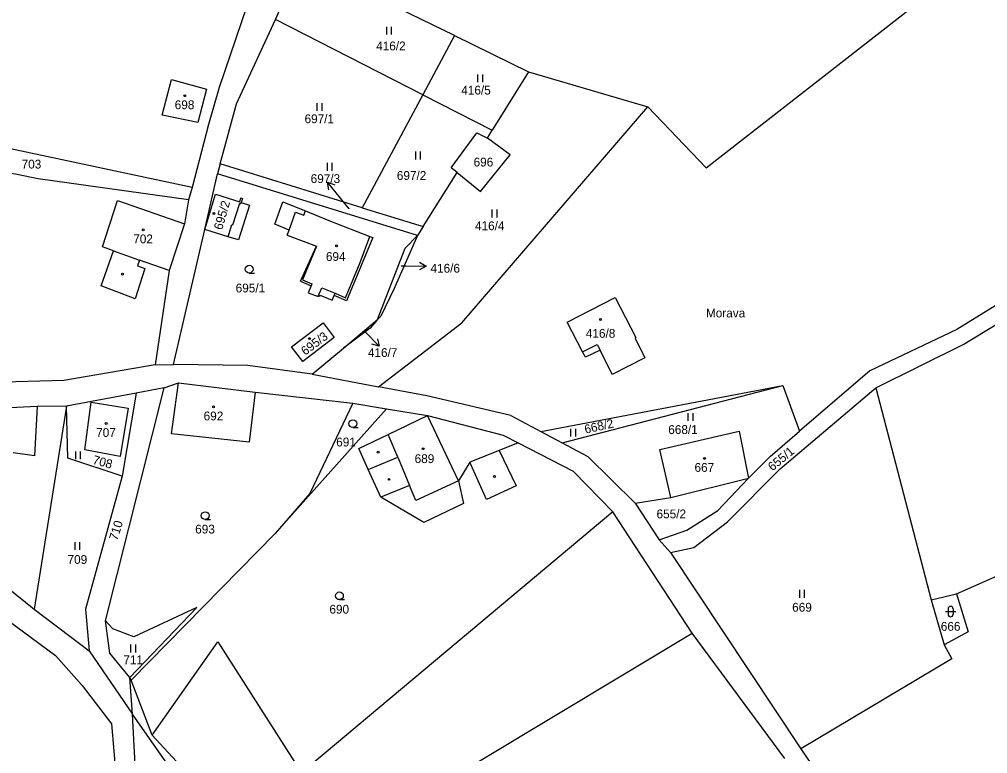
# Model space of a CAD drawing. Extents: x -670359 to -668019, y -978807 to -976674.
# Drawn here: x -668641.1 to -668454.3, y -977743.3 to -977601.7 of the extents above; entities that cross this region are included whole.
import ezdxf

# ---------------------------------------------------------------- set-up
doc = ezdxf.new("R2010")
doc.units = 0
for name, color, linetype in [('Hranice parcel', 7, 'Continuous'), ('Parcelní čísla', 7, 'Continuous'), ('Pop  PČ popisy', 7, 'Continuous'), ('Vnitřní kresba', 7, 'Continuous'), ('Značky budov', 7, 'Continuous'), ('Značky kultur', 7, 'Continuous')]:
    doc.layers.add(name, color=color, linetype=linetype)

msp = doc.modelspace()

# ---------------------------------------------------------------- linework, layer by layer
at = {"layer": 'Hranice parcel'}
for p, q in [((-668557.18, -977604.87), (-668586.71, -977590.44)), ((-668563.3, -977616.26), (-668591.75, -977601.77)), ((-668557.18, -977604.87), (-668563.3, -977616.26)), ((-668557.18, -977604.87), (-668542.9, -977611.84)), ((-668542.9, -977611.84), (-668519.87, -977618.61)), ((-668563.3, -977616.26), (-668575, -977638.05)), ((-668563.3, -977616.26), (-668549.89, -977623.09)), ((-668602.37, -977629.57), (-668599.22, -977618)), ((-668605.37, -977642.22), (-668602.9, -977631.5)), ((-668563.24, -977641.7), (-668556.67, -977631.25)), ((-668605.37, -977642.22), (-668603.32, -977635.42)), ((-668603.32, -977635.42), (-668598.63, -977636.89)), ((-668598.63, -977636.89), (-668598.41, -977636.17)), ((-668598.41, -977636.17), (-668598.11, -977636.26)), ((-668598.11, -977636.26), (-668598.36, -977637.06)), ((-668598.36, -977637.06), (-668596.76, -977637.56)), ((-668596.76, -977637.56), (-668598.87, -977644.27)), ((-668585.92, -977638.68), (-668581.45, -977640.5)), ((-668575, -977638.05), (-668563.24, -977641.7)), ((-668600.87, -977643.66), (-668605.37, -977642.22)), ((-668589.47, -977643.33), (-668589.11, -977642.36)), ((-668598.87, -977644.27), (-668600.87, -977643.66)), ((-668589.47, -977643.33), (-668583.84, -977645.49)), ((-668573.52, -977643.59), (-668572.97, -977643.8)), ((-668586.88, -977652.2), (-668584.86, -977653.08)), ((-668584.86, -977653.08), (-668585.39, -977654.43)), ((-668585.39, -977654.43), (-668583.52, -977655.19)), ((-668583.52, -977655.19), (-668583.44, -977655)), ((-668583.44, -977655), (-668583.18, -977655.11)), ((-668583.18, -977655.11), (-668583.09, -977654.89)), ((-668583.09, -977654.89), (-668580.76, -977655.85)), ((-668580.76, -977655.85), (-668580.41, -977655)), ((-668535.43, -977660.12), (-668526.2, -977655.34)), ((-668526.2, -977655.34), (-668522.22, -977663.1)), ((-668588.63, -977664.88), (-668582.54, -977660.26)), ((-668582.54, -977660.26), (-668580.43, -977663.1)), ((-668532.5, -977665.86), (-668535.43, -977660.12)), ((-668580.43, -977663.1), (-668586.44, -977667.7)), ((-668522.22, -977663.1), (-668522.33, -977663.17)), ((-668522.33, -977663.17), (-668520.43, -977666.96)), ((-668586.44, -977667.7), (-668588.63, -977664.88)), ((-668531.93, -977666.88), (-668532.5, -977665.86)), ((-668529.1, -977665.48), (-668531.93, -977666.88)), ((-668526.78, -977670.2), (-668529.1, -977665.48)), ((-668520.43, -977666.96), (-668526.78, -977670.2)), ((-668536.38, -977683.38), (-668493.85, -977672.35)), ((-668540.55, -977681.17), (-668536.38, -977683.38)), ((-668536.38, -977683.38), (-668531.45, -977686)), ((-668506.35, -977696.41), (-668500.44, -977690.21)), ((-668512.33, -977700.2), (-668506.35, -977696.41)), ((-668517.68, -977702.09), (-668512.33, -977700.2))]:
    msp.add_line(p, q, dxfattribs=at)
for points in [[(-668508.63, -977630.34), (-668419.28, -977560.69)], [(-668589.87, -977577.38), (-668602.57, -977614.87)], [(-668591.75, -977601.77), (-668586.71, -977590.44)], [(-668599.22, -977618), (-668591.75, -977601.77)], [(-668542.9, -977611.84), (-668549.89, -977623.09)], [(-668613.61, -977620.19), (-668611.77, -977613.34)], [(-668611.77, -977613.34), (-668605.01, -977615.16)], [(-668602.57, -977614.87), (-668604.65, -977622.03)], [(-668605.01, -977615.16), (-668606.68, -977621.61)], [(-668555.76, -977660.24), (-668519.87, -977618.61)], [(-668519.87, -977618.61), (-668508.63, -977630.34)], [(-668606.68, -977621.61), (-668613.61, -977620.19)], [(-668607.82, -977634.15), (-668664.97, -977621.98)], [(-668604.65, -977622.03), (-668607.82, -977634.15)], [(-668557.84, -977630.33), (-668552.87, -977623.62)], [(-668552.87, -977623.62), (-668550.83, -977624.66)], [(-668550.83, -977624.66), (-668549.89, -977623.09)], [(-668546.46, -977627.85), (-668550.83, -977624.66)], [(-668637.54, -977632.46), (-668666.42, -977626.62)], [(-668552.15, -977634.93), (-668546.46, -977627.85)], [(-668403.78, -977626.71), (-668460.27, -977661.53)], [(-668602.37, -977629.57), (-668602.9, -977631.5)], [(-668575, -977638.05), (-668602.37, -977629.57)], [(-668458.93, -977664.38), (-668402.04, -977629.73)], [(-668564.3, -977643.39), (-668602.9, -977631.5)], [(-668556.67, -977631.25), (-668557.84, -977630.33)], [(-668556.67, -977631.25), (-668552.15, -977634.93)], [(-668608.5, -977636.5), (-668637.54, -977632.46)], [(-668607.82, -977634.15), (-668608.5, -977636.5)], [(-668625.09, -977645.61), (-668622.18, -977636.66)], [(-668622.18, -977636.66), (-668609.3, -977641.17)], [(-668608.5, -977636.5), (-668609.3, -977641.17)], [(-668591.86, -977641.22), (-668590.3, -977636.9)], [(-668590.3, -977636.9), (-668585.92, -977638.68)], [(-668581.45, -977640.5), (-668573.52, -977643.59)], [(-668609.3, -977641.17), (-668612.22, -977650.13)], [(-668611.39, -977668.3), (-668605.37, -977642.22)], [(-668589.11, -977642.36), (-668591.86, -977641.22)], [(-668563.24, -977641.7), (-668564.3, -977643.39)], [(-668572.97, -977643.8), (-668578.04, -977656.03)], [(-668564.3, -977643.39), (-668568.85, -977653.65), (-668571.43, -977658.96), (-668572.07, -977659.62)], [(-668566.71, -977645.87), (-668564.3, -977643.39)], [(-668625.36, -977653.13), (-668623.01, -977646.34)], [(-668623.01, -977646.34), (-668625.09, -977645.61)], [(-668586.88, -977652.2), (-668583.84, -977645.49)], [(-668572.07, -977659.62), (-668566.71, -977645.87)], [(-668617.98, -977648.19), (-668618.38, -977649.23)], [(-668612.22, -977650.13), (-668617.98, -977648.19)], [(-668616.94, -977649.79), (-668618.8, -977655.63)], [(-668618.38, -977649.23), (-668616.94, -977649.79)], [(-668612.22, -977650.13), (-668614.92, -977668.36)], [(-668618.8, -977655.63), (-668625.36, -977653.13)], [(-668578.04, -977656.03), (-668580.41, -977655)], [(-668572.07, -977659.62), (-668573.45, -977661.25), (-668578.62, -977665.1)], [(-668578.62, -977665.1), (-668572.07, -977659.62)], [(-668571.86, -977672.56), (-668555.76, -977660.24)], [(-668460.27, -977661.53), (-668477.05, -977669.51)], [(-668584.63, -977670.12), (-668578.62, -977665.1)], [(-668475.88, -977672.75), (-668458.93, -977664.38)], [(-668614.92, -977668.36), (-668632.55, -977671.35)], [(-668614.92, -977668.36), (-668611.39, -977668.3)], [(-668597.06, -977668.49), (-668611.39, -977668.3)], [(-668584.63, -977670.12), (-668597.06, -977668.49)], [(-668584.63, -977670.12), (-668571.86, -977672.56)], [(-668477.05, -977669.51), (-668490.6, -977681.15)], [(-668632.55, -977671.35), (-668651.2, -977671.86)], [(-668613.23, -977672.8), (-668610.47, -977671.78)], [(-668611.78, -977681.65), (-668610.47, -977671.78)], [(-668610.47, -977671.78), (-668595.64, -977673.58)], [(-668562.51, -977674.34), (-668571.86, -977672.56)], [(-668540.55, -977681.17), (-668493.85, -977672.35)], [(-668494.37, -977688.42), (-668475.88, -977672.75)], [(-668493.85, -977672.35), (-668490.6, -977681.15)], [(-668475.88, -977672.75), (-668465.23, -977713.62)], [(-668618.62, -977673.79), (-668632.08, -977676.32)], [(-668624.53, -977717.7), (-668613.23, -977672.8)], [(-668618.62, -977673.79), (-668621.32, -977689.79)], [(-668613.23, -977672.8), (-668618.62, -977673.79)], [(-668595.64, -977673.58), (-668596.78, -977683.22)], [(-668595.64, -977673.58), (-668576.82, -977675.76)], [(-668546.31, -977678.11), (-668562.51, -977674.34)], [(-668637.69, -977676.34), (-668654.82, -977677.21)], [(-668632.08, -977676.32), (-668638.3, -977715.42)], [(-668637.69, -977676.34), (-668638.2, -977685.9)], [(-668632.08, -977676.32), (-668637.69, -977676.34)], [(-668631.79, -977686.32), (-668632.08, -977676.32)], [(-668628.51, -977684.73), (-668627.27, -977675.53)], [(-668627.27, -977675.53), (-668620.15, -977676.67)], [(-668576.82, -977675.76), (-668585.13, -977693.13)], [(-668576.82, -977675.76), (-668570.3, -977676.8)], [(-668620.15, -977676.67), (-668621.71, -977686.02)], [(-668570.3, -977676.8), (-668591.8, -977700.84)], [(-668570.3, -977676.8), (-668562.4, -977678.11)], [(-668569.98, -977681.76), (-668562.4, -977678.11)], [(-668562.4, -977678.11), (-668547.8, -977681.9)], [(-668546.31, -977678.11), (-668540.55, -977681.17)], [(-668596.78, -977683.22), (-668611.78, -977681.65)], [(-668575.65, -977684.5), (-668569.98, -977681.76)], [(-668547.8, -977681.9), (-668544.92, -977683.38)], [(-668517.55, -977684.65), (-668502.28, -977681.1)], [(-668502.28, -977681.1), (-668500.44, -977690.21)], [(-668496.29, -977686.04), (-668490.6, -977681.15)], [(-668544.92, -977683.38), (-668548.55, -977684.84)], [(-668544.92, -977683.38), (-668534.27, -977688.86)], [(-668638.2, -977685.9), (-668642.36, -977685.33)], [(-668621.71, -977686.02), (-668628.51, -977684.73)], [(-668573.82, -977688.51), (-668575.65, -977684.5)], [(-668548.55, -977684.84), (-668545.26, -977691.68)], [(-668515.47, -977693.92), (-668517.55, -977684.65)], [(-668621.32, -977689.79), (-668631.79, -977686.32)], [(-668554.23, -977687.12), (-668556.44, -977690.72)], [(-668551.04, -977694.27), (-668554.23, -977687.12)], [(-668531.45, -977686), (-668522.32, -977695.04)], [(-668500.44, -977690.21), (-668496.29, -977686.04)], [(-668571.37, -977693.88), (-668573.82, -977688.51)], [(-668534.27, -977688.86), (-668526.62, -977696.65)], [(-668504.5, -977698.63), (-668494.37, -977688.42)], [(-668621.32, -977689.79), (-668628.41, -977715.46)], [(-668556.44, -977690.72), (-668555.47, -977695.08)], [(-668515.47, -977693.92), (-668500.44, -977690.21)], [(-668585.13, -977693.13), (-668591.8, -977700.84)], [(-668545.26, -977691.68), (-668551.04, -977694.27)], [(-668563.13, -977698.73), (-668571.37, -977693.88)], [(-668555.47, -977695.08), (-668563.13, -977698.73)], [(-668522.32, -977695.04), (-668515.47, -977693.92)], [(-668522.32, -977695.04), (-668517.68, -977702.09)], [(-668526.62, -977696.65), (-668586.69, -977746.97)], [(-668511.35, -977720.08), (-668526.62, -977696.65)], [(-668659.7, -977698.24), (-668638.3, -977715.42)], [(-668511, -977703.53), (-668504.5, -977698.63)], [(-668591.8, -977700.84), (-668619.55, -977729.15)], [(-668517.68, -977702.09), (-668515.52, -977704.49)], [(-668515.52, -977704.49), (-668511, -977703.53)], [(-668515.52, -977704.49), (-668490.35, -977742.35)], [(-668460.3, -977712.51), (-668440.7, -977703.84)], [(-668654.53, -977709.38), (-668634.16, -977724.39)], [(-668465.23, -977713.62), (-668460.3, -977712.51)], [(-668465.23, -977713.62), (-668462.73, -977722.35)], [(-668460.3, -977712.51), (-668458.08, -977719.79)], [(-668638.3, -977715.42), (-668631.43, -977720.64)], [(-668628.41, -977715.46), (-668627.68, -977723.45)], [(-668619.85, -977728.6), (-668606.9, -977715.15)], [(-668606.9, -977715.15), (-668619.09, -977720.77)], [(-668623.67, -977723.94), (-668624.53, -977717.7)], [(-668624.53, -977717.7), (-668623.1, -977719.25)], [(-668619.09, -977720.77), (-668623.1, -977719.25)], [(-668631.43, -977720.64), (-668627.68, -977723.45)], [(-668493.46, -977744.24), (-668511.35, -977720.08)], [(-668458.08, -977719.79), (-668462.73, -977722.35)], [(-668462.73, -977722.35), (-668461.23, -977725.04)], [(-668634.16, -977724.39), (-668629.06, -977730.17)], [(-668627.68, -977723.45), (-668619.3, -977735.7)], [(-668619.85, -977728.6), (-668623.67, -977723.94)], [(-668461.23, -977725.04), (-668490.35, -977742.35)], [(-668619.55, -977729.15), (-668619.85, -977728.6)], [(-668619.3, -977735.7), (-668619.85, -977728.6)], [(-668629.06, -977730.17), (-668623.4, -977737.55)], [(-668615.55, -977739.75), (-668619.55, -977729.15)], [(-668591.77, -977775.03), (-668619.3, -977735.7)], [(-668618.64, -977749.04), (-668619.3, -977735.7)], [(-668623.4, -977737.55), (-668622.47, -977748.11)], [(-668599.16, -977757.41), (-668615.55, -977739.75)], [(-668490.35, -977742.35), (-668466.44, -977777.44)]]:
    msp.add_lwpolyline(points, dxfattribs=at)
at = {"layer": 'Parcelní čísla'}
for p, q in [((-668581.44, -977634.57), (-668581.66, -977633.09)), ((-668577.54, -977638.27), (-668579.17, -977636.22)), ((-668567.46, -977649.26), (-668566.65, -977649.27)), ((-668563.94, -977648.54), (-668562.65, -977649.31)), ((-668574.52, -977661.85), (-668574.49, -977661.89)), ((-668572.07, -977663.31), (-668571.71, -977664.76))]:
    msp.add_line(p, q, dxfattribs=at)
for points in [[(-668579.17, -977636.22), (-668581.66, -977633.09), (-668580.26, -977633.64)], [(-668566.65, -977649.27), (-668562.65, -977649.31), (-668563.96, -977650.04)], [(-668574.49, -977661.89), (-668571.71, -977664.76), (-668573.15, -977664.35)]]:
    msp.add_lwpolyline(points, dxfattribs=at)
at = {"layer": 'Vnitřní kresba'}
for p, q in [((-668599.96, -977641.32), (-668598.62, -977637.2)), ((-668598.62, -977637.2), (-668598.43, -977637.27)), ((-668598.43, -977637.27), (-668598.36, -977637.06)), ((-668589.11, -977642.36), (-668587.84, -977638.9)), ((-668587.84, -977638.9), (-668586.23, -977639.49)), ((-668586.23, -977639.49), (-668585.92, -977638.68)), ((-668600.87, -977643.66), (-668600.13, -977641.27)), ((-668600.13, -977641.27), (-668599.96, -977641.32)), ((-668575.37, -977648.62), (-668573.52, -977643.59)), ((-668583.84, -977645.49), (-668586.53, -977651.98)), ((-668578.2, -977655.4), (-668575.37, -977648.62)), ((-668586.53, -977651.98), (-668584.71, -977652.7)), ((-668584.71, -977652.7), (-668584.86, -977653.08)), ((-668583.44, -977655), (-668582.8, -977653.47)), ((-668582.8, -977653.47), (-668580.23, -977654.55)), ((-668580.23, -977654.55), (-668578.2, -977655.4)), ((-668532.5, -977665.86), (-668529.63, -977664.39)), ((-668529.63, -977664.39), (-668529.1, -977665.48))]:
    msp.add_line(p, q, dxfattribs=at)
for points in [[(-668623.01, -977646.34), (-668617.98, -977648.19)], [(-668580.41, -977655), (-668580.23, -977654.55)], [(-668556.44, -977690.72), (-668562.4, -977678.11)], [(-668568.15, -977686.15), (-668569.98, -977681.76)], [(-668548.55, -977684.84), (-668554.23, -977687.12)], [(-668573.82, -977688.51), (-668568.15, -977686.15)], [(-668568.15, -977686.15), (-668565.88, -977691.59)], [(-668556.44, -977690.72), (-668564.66, -977694.52)], [(-668565.88, -977691.59), (-668571.37, -977693.88)], [(-668564.66, -977694.52), (-668565.88, -977691.59)], [(-668578.19, -977760.23), (-668511.35, -977720.08)], [(-668615.55, -977739.75), (-668602.87, -977721.74)], [(-668602.87, -977721.74), (-668586.69, -977746.97)]]:
    msp.add_lwpolyline(points, dxfattribs=at)
at = {"layer": 'Značky budov'}
for centre in [(-668609.24, -977616.45), (-668603.6, -977639.16), (-668617.24, -977642.31), (-668579.93, -977645.41), (-668529.04, -977659.6), (-668585.16, -977663.28), (-668603.66, -977676.45), (-668624.4, -977679.64), (-668563.23, -977684.51), (-668508.94, -977686.37)]:
    msp.add_circle(centre, 0.175, dxfattribs=at)
at = {"layer": 'Značky kultur'}
for p, q in [((-668570.31, -977603.15), (-668570.31, -977604.65)), ((-668569.31, -977604.65), (-668569.31, -977603.15)), ((-668552.73, -977612.36), (-668552.73, -977613.86)), ((-668551.73, -977613.86), (-668551.73, -977612.36)), ((-668583.74, -977617.88), (-668583.74, -977619.38)), ((-668582.74, -977619.38), (-668582.74, -977617.88)), ((-668564.74, -977627.24), (-668564.74, -977628.74)), ((-668563.74, -977628.74), (-668563.74, -977627.24)), ((-668581.76, -977629.42), (-668581.76, -977630.92)), ((-668580.76, -977630.92), (-668580.76, -977629.42)), ((-668549.95, -977638.41), (-668549.95, -977639.91)), ((-668548.95, -977639.91), (-668548.95, -977638.41)), ((-668596.8, -977650.65), (-668595.8, -977650.65)), ((-668512.15, -977677.66), (-668512.15, -977679.16)), ((-668511.15, -977679.16), (-668511.15, -977677.66)), ((-668576.8, -977680.42), (-668575.8, -977680.42)), ((-668534.8, -977680.66), (-668534.8, -977682.16)), ((-668533.8, -977682.16), (-668533.8, -977680.66)), ((-668630.33, -977685.02), (-668630.33, -977686.52)), ((-668629.33, -977686.52), (-668629.33, -977685.02)), ((-668605.29, -977698.16), (-668604.29, -977698.16)), ((-668630.46, -977702.52), (-668630.46, -977704.02)), ((-668629.46, -977704.02), (-668629.46, -977702.52)), ((-668490.64, -977711.73), (-668490.64, -977713.23)), ((-668489.64, -977713.23), (-668489.64, -977711.73)), ((-668579.39, -977713.61), (-668578.39, -977713.61)), ((-668461.96, -977715.41), (-668461.96, -977716.41)), ((-668460.96, -977715.41), (-668460.96, -977716.41)), ((-668462.46, -977715.91), (-668460.46, -977715.91)), ((-668619.69, -977722.28), (-668619.69, -977723.78)), ((-668618.69, -977723.78), (-668618.69, -977722.28))]:
    msp.add_line(p, q, dxfattribs=at)
for centre, radius in [((-668609.24, -977616.45), 0.175), ((-668603.6, -977639.16), 0.175), ((-668617.24, -977642.31), 0.175), ((-668579.93, -977645.41), 0.175), ((-668596.8, -977649.9), 0.75), ((-668621.25, -977650.85), 0.175), ((-668529.04, -977659.6), 0.175), ((-668585.16, -977663.28), 0.175), ((-668603.66, -977676.45), 0.175), ((-668624.4, -977679.64), 0.175), ((-668576.8, -977679.67), 0.75), ((-668571.92, -977685.18), 0.175), ((-668563.23, -977684.51), 0.175), ((-668508.94, -977686.37), 0.175), ((-668569.82, -977690.43), 0.175), ((-668549.48, -977689.86), 0.175), ((-668605.29, -977697.41), 0.75), ((-668579.39, -977712.86), 0.75)]:
    msp.add_circle(centre, radius, dxfattribs=at)
for centre, start, end in [((-668461.46, -977715.41), 0, 180), ((-668461.46, -977716.41), 180, 0)]:
    msp.add_arc(centre, 0.5, start, end, dxfattribs=at)

# ---------------------------------------------------------------- texts
at = {"layer": 'Parcelní čísla'}
for s, height, p in [('416/2', 1.7, (-668572.3, -977607.71)), ('416/5', 1.7, (-668555.88, -977616.23)), ('698', 1.7, (-668611.17, -977619.05)), ('697/1', 1.7, (-668586.12, -977621.75)), ('703', 1.7, (-668640.71, -977630.49)), ('696', 1.7, (-668553.5, -977630.1)), ('697/3', 1.7, (-668584.94, -977633.29)), ('697/2', 1.7, (-668568.31, -977632.68)), ('697/3', 0.1, (-668577.54, -977638.27)), ('416/4', 1.7, (-668553.23, -977642.38)), ('702', 1.7, (-668619.17, -977644.91)), ('694', 1.7, (-668582, -977648.31)), ('416/6', 0.1, (-668567.65, -977649.26)), ('416/6', 1.7, (-668561.82, -977650.57)), ('695/1', 1.7, (-668599.41, -977654.38)), ('416/8', 1.7, (-668531.84, -977663.12)), ('416/7', 0.1, (-668574.71, -977661.85)), ('416/7', 1.7, (-668573.89, -977666.83)), ('692', 1.7, (-668605.59, -977679.05)), ('668/1', 1.7, (-668515.94, -977681.67)), ('707', 1.7, (-668626.33, -977682.24)), ('691', 1.7, (-668580.01, -977684.08)), ('689', 1.7, (-668564.88, -977687.28)), ('667', 1.7, (-668510.87, -977688.97)), ('655/2', 1.7, (-668518.2, -977697.93)), ('693', 1.7, (-668607.22, -977700.86)), ('709', 1.7, (-668631.85, -977706.72)), ('690', 1.7, (-668581.32, -977716.31)), ('669', 1.7, (-668492.03, -977715.93)), ('666', 1.7, (-668463.35, -977719.61)), ('711', 1.7, (-668621.08, -977726.05))]:
    msp.add_text(s, height=height, dxfattribs=at).set_placement(p)
for s, rotation, p in [('695/2', 74, (-668602.03, -977642.45)), ('695/3', 36.8, (-668585.99, -977666.61)), ('668/2', 12.6, (-668531.91, -977681.63)), ('708', 344.6591, (-668627.12, -977687.39)), ('655/1', 39.6, (-668495.84, -977688.91)), ('710', 72.6844, (-668622.26, -977702.31))]:
    msp.add_text(s, height=1.7, rotation=rotation, dxfattribs=at).set_placement(p)
at = {"layer": 'Pop  PČ popisy'}
msp.add_text('Morava', height=1.7, dxfattribs=at).set_placement((-668508.67, -977659.2))

doc.saveas('drawing.dxf')
